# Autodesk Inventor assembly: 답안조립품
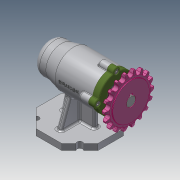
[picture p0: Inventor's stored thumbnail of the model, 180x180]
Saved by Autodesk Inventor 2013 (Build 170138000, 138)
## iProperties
Created: 2021-01
Part Number: 답안조립품
Document SubType Name: Assembly
Designer: user
Author: user
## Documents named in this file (12)
- C:\Users\user\Desktop\710106V1007\답안조립품.iam
- C:\Users\user\Desktop\710106V1007\본체.ipt
- C:\Users\user\Desktop\710106V1007\멈춤나사 M3.ipt
- C:\Users\user\Desktop\710106V1007\베어링 6004.ipt
- C:\Users\user\Desktop\710106V1007\베어링 51202.ipt
- C:\Users\user\Desktop\710106V1007\볼트 M4.ipt
- C:\Users\user\Desktop\710106V1007\스프로킷.ipt
- C:\Users\user\Desktop\710106V1007\어댑터슬리브.ipt
- C:\Users\user\Desktop\710106V1007\오일 실.ipt
- C:\Users\user\Desktop\710106V1007\축.ipt
- C:\Users\user\Desktop\710106V1007\커버.ipt
- C:\Users\user\Desktop\710106V1007\키 5 x 5 x 14.ipt
